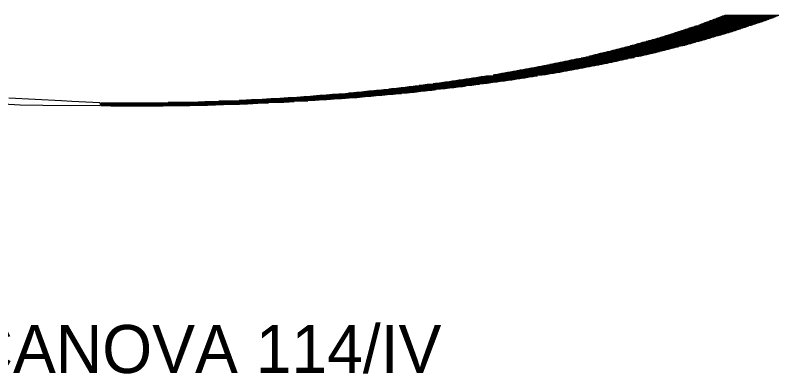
# Model space of a CAD drawing. Extents: x -706655 to -706193, y -1036183 to -1035040.
# Drawn here: x -706307.75 to -706295.83, y -1035256.56 to -1035250.97 of the extents above; entities that cross this region are included whole.
import ezdxf

# ---------------------------------------------------------------- set-up
doc = ezdxf.new("R2010")
doc.units = 0
doc.layers.add('Vrstva 54', color=7, linetype='Continuous')

msp = doc.modelspace()

# ---------------------------------------------------------------- linework, layer by layer
at = {"layer": 'Vrstva 54'}
for p, q in [((-706296.695, -1035250.975), (-706295.853, -1035250.975)), ((-706296.685, -1035250.971), (-706295.842, -1035250.971)), ((-706296.674, -1035250.968), (-706295.83, -1035250.968)), ((-706297.006, -1035251.091), (-706296.173, -1035251.091)), ((-706296.995, -1035251.088), (-706296.161, -1035251.088)), ((-706296.983, -1035251.082), (-706296.149, -1035251.082)), ((-706296.973, -1035251.08), (-706296.137, -1035251.08)), ((-706296.962, -1035251.075), (-706296.126, -1035251.075)), ((-706296.951, -1035251.07), (-706296.113, -1035251.07)), ((-706296.941, -1035251.068), (-706296.101, -1035251.068)), ((-706296.929, -1035251.063), (-706296.088, -1035251.063)), ((-706296.92, -1035251.059), (-706296.076, -1035251.059)), ((-706296.909, -1035251.055), (-706296.064, -1035251.055)), ((-706296.899, -1035251.052), (-706296.052, -1035251.052)), ((-706296.888, -1035251.048), (-706296.041, -1035251.048)), ((-706296.877, -1035251.043), (-706296.029, -1035251.043)), ((-706296.867, -1035251.04), (-706296.019, -1035251.04)), ((-706296.856, -1035251.036), (-706296.008, -1035251.036)), ((-706296.844, -1035251.031), (-706295.997, -1035251.031)), ((-706296.835, -1035251.027), (-706295.987, -1035251.027)), ((-706296.814, -1035251.02), (-706295.965, -1035251.02)), ((-706296.803, -1035251.015), (-706295.957, -1035251.015)), ((-706296.793, -1035251.013), (-706295.946, -1035251.013)), ((-706296.781, -1035251.008), (-706295.935, -1035251.008)), ((-706296.771, -1035251.004), (-706295.926, -1035251.004)), ((-706296.76, -1035251.001), (-706295.914, -1035251.001)), ((-706296.749, -1035250.994), (-706295.903, -1035250.994)), ((-706296.739, -1035250.992), (-706295.893, -1035250.992)), ((-706296.727, -1035250.987), (-706295.883, -1035250.987)), ((-706296.717, -1035250.984), (-706295.874, -1035250.984)), ((-706296.707, -1035250.979), (-706295.863, -1035250.979)), ((-706297.361, -1035251.21), (-706296.536, -1035251.21)), ((-706297.347, -1035251.208), (-706296.524, -1035251.208)), ((-706297.335, -1035251.203), (-706296.512, -1035251.203)), ((-706297.324, -1035251.198), (-706296.499, -1035251.198)), ((-706297.311, -1035251.196), (-706296.487, -1035251.196)), ((-706297.299, -1035251.192), (-706296.475, -1035251.192)), ((-706297.287, -1035251.186), (-706296.463, -1035251.186)), ((-706297.275, -1035251.184), (-706296.452, -1035251.184)), ((-706297.262, -1035251.179), (-706296.439, -1035251.179)), ((-706297.25, -1035251.177), (-706296.428, -1035251.177)), ((-706297.238, -1035251.171), (-706296.415, -1035251.171)), ((-706297.225, -1035251.166), (-706296.402, -1035251.166)), ((-706297.213, -1035251.163), (-706296.391, -1035251.163)), ((-706297.201, -1035251.159), (-706296.38, -1035251.159)), ((-706297.188, -1035251.155), (-706296.367, -1035251.155)), ((-706297.176, -1035251.152), (-706296.356, -1035251.152)), ((-706297.163, -1035251.147), (-706296.343, -1035251.147)), ((-706297.151, -1035251.145), (-706296.33, -1035251.145)), ((-706297.14, -1035251.14), (-706296.319, -1035251.14)), ((-706297.127, -1035251.135), (-706296.307, -1035251.135)), ((-706297.115, -1035251.132), (-706296.295, -1035251.132)), ((-706297.081, -1035251.12), (-706296.259, -1035251.12)), ((-706297.07, -1035251.115), (-706296.247, -1035251.115)), ((-706297.059, -1035251.112), (-706296.234, -1035251.112)), ((-706297.049, -1035251.106), (-706296.222, -1035251.106)), ((-706297.038, -1035251.103), (-706296.21, -1035251.103)), ((-706297.027, -1035251.101), (-706296.198, -1035251.101)), ((-706297.017, -1035251.095), (-706296.186, -1035251.095)), ((-706297.741, -1035251.33), (-706296.943, -1035251.33)), ((-706297.727, -1035251.327), (-706296.927, -1035251.327)), ((-706297.713, -1035251.323), (-706296.914, -1035251.323)), ((-706297.699, -1035251.32), (-706296.9, -1035251.32)), ((-706297.683, -1035251.314), (-706296.886, -1035251.314)), ((-706297.67, -1035251.312), (-706296.873, -1035251.312)), ((-706297.655, -1035251.306), (-706296.859, -1035251.306)), ((-706297.642, -1035251.305), (-706296.844, -1035251.305)), ((-706297.63, -1035251.299), (-706296.831, -1035251.299)), ((-706297.618, -1035251.295), (-706296.818, -1035251.295)), ((-706297.605, -1035251.291), (-706296.805, -1035251.291)), ((-706297.593, -1035251.286), (-706296.79, -1035251.286)), ((-706297.581, -1035251.283), (-706296.778, -1035251.283)), ((-706297.568, -1035251.279), (-706296.762, -1035251.279)), ((-706297.557, -1035251.275), (-706296.748, -1035251.275)), ((-706297.544, -1035251.271), (-706296.734, -1035251.271)), ((-706297.532, -1035251.268), (-706296.721, -1035251.268)), ((-706297.52, -1035251.263), (-706296.708, -1035251.263)), ((-706297.506, -1035251.259), (-706296.693, -1035251.259)), ((-706297.494, -1035251.256), (-706296.68, -1035251.256)), ((-706297.482, -1035251.251), (-706296.666, -1035251.251)), ((-706297.47, -1035251.247), (-706296.653, -1035251.247)), ((-706297.459, -1035251.244), (-706296.639, -1035251.244)), ((-706297.446, -1035251.238), (-706296.626, -1035251.238)), ((-706297.433, -1035251.236), (-706296.611, -1035251.236)), ((-706297.421, -1035251.23), (-706296.598, -1035251.23)), ((-706297.409, -1035251.229), (-706296.584, -1035251.229)), ((-706297.398, -1035251.223), (-706296.572, -1035251.223)), ((-706297.384, -1035251.219), (-706296.56, -1035251.219)), ((-706297.373, -1035251.216), (-706296.548, -1035251.216)), ((-706298.158, -1035251.447), (-706297.362, -1035251.447)), ((-706298.145, -1035251.442), (-706297.346, -1035251.442)), ((-706298.13, -1035251.439), (-706297.33, -1035251.439)), ((-706298.117, -1035251.435), (-706297.315, -1035251.435)), ((-706298.102, -1035251.432), (-706297.299, -1035251.432)), ((-706298.087, -1035251.427), (-706297.284, -1035251.427)), ((-706298.073, -1035251.423), (-706297.268, -1035251.423)), ((-706298.058, -1035251.42), (-706297.251, -1035251.42)), ((-706298.044, -1035251.414), (-706297.237, -1035251.414)), ((-706298.03, -1035251.41), (-706297.22, -1035251.41)), ((-706298.015, -1035251.407), (-706297.205, -1035251.407)), ((-706298.001, -1035251.402), (-706297.19, -1035251.402)), ((-706297.986, -1035251.4), (-706297.176, -1035251.4)), ((-706297.972, -1035251.395), (-706297.162, -1035251.395)), ((-706297.958, -1035251.39), (-706297.148, -1035251.39)), ((-706297.944, -1035251.388), (-706297.135, -1035251.388)), ((-706297.928, -1035251.383), (-706297.121, -1035251.383)), ((-706297.899, -1035251.374), (-706297.092, -1035251.374)), ((-706297.886, -1035251.37), (-706297.079, -1035251.37)), ((-706297.871, -1035251.367), (-706297.065, -1035251.367)), ((-706297.857, -1035251.363), (-706297.051, -1035251.363)), ((-706297.841, -1035251.36), (-706297.038, -1035251.36)), ((-706297.828, -1035251.356), (-706297.025, -1035251.356)), ((-706297.813, -1035251.35), (-706297.01, -1035251.35)), ((-706297.8, -1035251.346), (-706296.996, -1035251.346)), ((-706297.786, -1035251.344), (-706296.983, -1035251.344)), ((-706297.77, -1035251.339), (-706296.97, -1035251.339)), ((-706297.755, -1035251.335), (-706296.955, -1035251.335)), ((-706298.65, -1035251.57), (-706297.852, -1035251.57)), ((-706298.635, -1035251.566), (-706297.834, -1035251.566)), ((-706298.619, -1035251.562), (-706297.819, -1035251.562)), ((-706298.602, -1035251.559), (-706297.802, -1035251.559)), ((-706298.585, -1035251.555), (-706297.787, -1035251.555)), ((-706298.569, -1035251.55), (-706297.772, -1035251.55)), ((-706298.553, -1035251.547), (-706297.755, -1035251.547)), ((-706298.537, -1035251.543), (-706297.74, -1035251.543)), ((-706298.521, -1035251.538), (-706297.724, -1035251.538)), ((-706298.505, -1035251.534), (-706297.709, -1035251.534)), ((-706298.488, -1035251.531), (-706297.694, -1035251.531)), ((-706298.456, -1035251.523), (-706297.661, -1035251.523)), ((-706298.438, -1035251.518), (-706297.646, -1035251.518)), ((-706298.423, -1035251.514), (-706297.63, -1035251.514)), ((-706298.407, -1035251.512), (-706297.614, -1035251.512)), ((-706298.391, -1035251.507), (-706297.598, -1035251.507)), ((-706298.376, -1035251.503), (-706297.582, -1035251.503)), ((-706298.358, -1035251.497), (-706297.567, -1035251.497)), ((-706298.342, -1035251.495), (-706297.551, -1035251.495)), ((-706298.326, -1035251.49), (-706297.536, -1035251.49)), ((-706298.31, -1035251.486), (-706297.52, -1035251.486)), ((-706298.294, -1035251.483), (-706297.504, -1035251.483)), ((-706298.278, -1035251.478), (-706297.489, -1035251.478)), ((-706298.262, -1035251.474), (-706297.473, -1035251.474)), ((-706298.245, -1035251.471), (-706297.457, -1035251.471)), ((-706298.232, -1035251.467), (-706297.442, -1035251.467)), ((-706298.217, -1035251.463), (-706297.424, -1035251.463)), ((-706298.204, -1035251.46), (-706297.409, -1035251.46)), ((-706298.188, -1035251.455), (-706297.393, -1035251.455)), ((-706299.189, -1035251.69), (-706298.402, -1035251.69)), ((-706299.169, -1035251.686), (-706298.383, -1035251.686)), ((-706299.15, -1035251.683), (-706298.365, -1035251.683)), ((-706299.13, -1035251.678), (-706298.346, -1035251.678)), ((-706299.109, -1035251.676), (-706298.329, -1035251.676)), ((-706299.091, -1035251.67), (-706298.31, -1035251.67)), ((-706299.071, -1035251.665), (-706298.293, -1035251.665)), ((-706299.052, -1035251.662), (-706298.273, -1035251.662)), ((-706299.032, -1035251.657), (-706298.255, -1035251.657)), ((-706299.013, -1035251.655), (-706298.237, -1035251.655)), ((-706298.993, -1035251.65), (-706298.218, -1035251.65)), ((-706298.974, -1035251.646), (-706298.2, -1035251.646)), ((-706298.953, -1035251.643), (-706298.181, -1035251.643)), ((-706298.915, -1035251.633), (-706298.145, -1035251.633)), ((-706298.896, -1035251.631), (-706298.128, -1035251.631)), ((-706298.877, -1035251.627), (-706298.109, -1035251.627)), ((-706298.861, -1035251.625), (-706298.09, -1035251.625)), ((-706298.844, -1035251.618), (-706298.071, -1035251.618)), ((-706298.796, -1035251.606), (-706298.016, -1035251.606)), ((-706298.78, -1035251.603), (-706297.997, -1035251.603)), ((-706298.764, -1035251.599), (-706297.98, -1035251.599)), ((-706298.747, -1035251.594), (-706297.962, -1035251.594)), ((-706298.731, -1035251.592), (-706297.944, -1035251.592)), ((-706298.716, -1035251.586), (-706297.925, -1035251.586)), ((-706298.699, -1035251.582), (-706297.906, -1035251.582)), ((-706298.682, -1035251.578), (-706297.889, -1035251.578)), ((-706298.666, -1035251.575), (-706297.871, -1035251.575)), ((-706299.803, -1035251.81), (-706299.017, -1035251.81)), ((-706299.78, -1035251.805), (-706298.996, -1035251.805)), ((-706299.758, -1035251.803), (-706298.975, -1035251.803)), ((-706299.736, -1035251.798), (-706298.953, -1035251.798)), ((-706299.715, -1035251.793), (-706298.932, -1035251.793)), ((-706299.692, -1035251.79), (-706298.911, -1035251.79)), ((-706299.67, -1035251.786), (-706298.89, -1035251.786)), ((-706299.649, -1035251.783), (-706298.869, -1035251.783)), ((-706299.626, -1035251.779), (-706298.847, -1035251.779)), ((-706299.604, -1035251.773), (-706298.826, -1035251.773)), ((-706299.582, -1035251.77), (-706298.805, -1035251.77)), ((-706299.56, -1035251.766), (-706298.785, -1035251.766)), ((-706299.541, -1035251.761), (-706298.763, -1035251.761)), ((-706299.521, -1035251.759), (-706298.742, -1035251.759)), ((-706299.501, -1035251.754), (-706298.721, -1035251.754)), ((-706299.481, -1035251.751), (-706298.701, -1035251.751)), ((-706299.462, -1035251.746), (-706298.679, -1035251.746)), ((-706299.441, -1035251.742), (-706298.658, -1035251.742)), ((-706299.423, -1035251.739), (-706298.636, -1035251.739)), ((-706299.404, -1035251.733), (-706298.615, -1035251.733)), ((-706299.385, -1035251.729), (-706298.594, -1035251.729)), ((-706299.364, -1035251.726), (-706298.573, -1035251.726)), ((-706299.344, -1035251.722), (-706298.552, -1035251.722)), ((-706299.325, -1035251.718), (-706298.531, -1035251.718)), ((-706299.305, -1035251.715), (-706298.512, -1035251.715)), ((-706299.287, -1035251.71), (-706298.494, -1035251.71)), ((-706299.265, -1035251.707), (-706298.476, -1035251.707)), ((-706299.246, -1035251.701), (-706298.458, -1035251.701)), ((-706299.227, -1035251.698), (-706298.438, -1035251.698)), ((-706299.209, -1035251.694), (-706298.42, -1035251.694)), ((-706300.478, -1035251.925), (-706299.698, -1035251.925)), ((-706300.45, -1035251.922), (-706299.673, -1035251.922)), ((-706300.424, -1035251.918), (-706299.649, -1035251.918)), ((-706300.398, -1035251.912), (-706299.624, -1035251.912)), ((-706300.372, -1035251.911), (-706299.598, -1035251.911)), ((-706300.292, -1035251.898), (-706299.523, -1035251.898)), ((-706300.267, -1035251.893), (-706299.498, -1035251.893)), ((-706300.244, -1035251.89), (-706299.474, -1035251.89)), ((-706300.221, -1035251.886), (-706299.448, -1035251.886)), ((-706300.2, -1035251.882), (-706299.423, -1035251.882)), ((-706300.177, -1035251.879), (-706299.399, -1035251.879)), ((-706300.156, -1035251.874), (-706299.374, -1035251.874)), ((-706300.134, -1035251.87), (-706299.349, -1035251.87)), ((-706300.111, -1035251.866), (-706299.324, -1035251.866)), ((-706300.09, -1035251.861), (-706299.3, -1035251.861)), ((-706300.068, -1035251.858), (-706299.273, -1035251.858)), ((-706300.046, -1035251.855), (-706299.249, -1035251.855)), ((-706300.023, -1035251.85), (-706299.228, -1035251.85)), ((-706300.001, -1035251.848), (-706299.207, -1035251.848)), ((-706299.979, -1035251.842), (-706299.185, -1035251.842)), ((-706299.934, -1035251.835), (-706299.144, -1035251.835)), ((-706299.913, -1035251.829), (-706299.122, -1035251.829)), ((-706299.891, -1035251.826), (-706299.1, -1035251.826)), ((-706299.869, -1035251.822), (-706299.08, -1035251.822)), ((-706299.847, -1035251.818), (-706299.059, -1035251.818)), ((-706299.824, -1035251.815), (-706299.038, -1035251.815)), ((-706301.319, -1035252.046), (-706300.532, -1035252.046)), ((-706301.287, -1035252.042), (-706300.502, -1035252.042)), ((-706301.225, -1035252.035), (-706300.442, -1035252.035)), ((-706301.193, -1035252.029), (-706300.414, -1035252.029)), ((-706301.161, -1035252.026), (-706300.384, -1035252.026)), ((-706301.13, -1035252.022), (-706300.354, -1035252.022)), ((-706301.099, -1035252.018), (-706300.325, -1035252.018)), ((-706301.068, -1035252.014), (-706300.295, -1035252.014)), ((-706301.036, -1035252.009), (-706300.264, -1035252.009)), ((-706301.004, -1035252.007), (-706300.235, -1035252.007)), ((-706300.977, -1035252.001), (-706300.205, -1035252.001)), ((-706300.951, -1035251.998), (-706300.175, -1035251.998)), ((-706300.925, -1035251.993), (-706300.146, -1035251.993)), ((-706300.898, -1035251.99), (-706300.115, -1035251.99)), ((-706300.872, -1035251.985), (-706300.086, -1035251.985)), ((-706300.845, -1035251.983), (-706300.056, -1035251.983)), ((-706300.819, -1035251.977), (-706300.027, -1035251.977)), ((-706300.793, -1035251.975), (-706299.998, -1035251.975)), ((-706300.766, -1035251.97), (-706299.973, -1035251.97)), ((-706300.74, -1035251.966), (-706299.948, -1035251.966)), ((-706300.714, -1035251.962), (-706299.923, -1035251.962)), ((-706300.661, -1035251.953), (-706299.872, -1035251.953)), ((-706300.635, -1035251.951), (-706299.848, -1035251.951)), ((-706300.608, -1035251.946), (-706299.823, -1035251.946)), ((-706300.583, -1035251.943), (-706299.798, -1035251.943)), ((-706300.556, -1035251.938), (-706299.773, -1035251.938)), ((-706300.529, -1035251.933), (-706299.749, -1035251.933)), ((-706300.503, -1035251.931), (-706299.724, -1035251.931)), ((-706302.389, -1035252.166), (-706301.523, -1035252.166)), ((-706302.348, -1035252.162), (-706301.488, -1035252.162)), ((-706302.309, -1035252.156), (-706301.454, -1035252.156)), ((-706302.27, -1035252.155), (-706301.419, -1035252.155)), ((-706302.231, -1035252.15), (-706301.384, -1035252.15)), ((-706302.192, -1035252.145), (-706301.351, -1035252.145)), ((-706302.153, -1035252.141), (-706301.317, -1035252.141)), ((-706302.114, -1035252.137), (-706301.282, -1035252.137)), ((-706302.075, -1035252.135), (-706301.248, -1035252.135)), ((-706302.035, -1035252.13), (-706301.212, -1035252.13)), ((-706301.996, -1035252.126), (-706301.18, -1035252.126)), ((-706301.918, -1035252.118), (-706301.111, -1035252.118)), ((-706301.879, -1035252.113), (-706301.076, -1035252.113)), ((-706301.84, -1035252.111), (-706301.041, -1035252.111)), ((-706301.8, -1035252.105), (-706301.009, -1035252.105)), ((-706301.761, -1035252.103), (-706300.974, -1035252.103)), ((-706301.729, -1035252.097), (-706300.939, -1035252.097)), ((-706301.697, -1035252.094), (-706300.905, -1035252.094)), ((-706301.666, -1035252.088), (-706300.871, -1035252.088)), ((-706301.634, -1035252.085), (-706300.837, -1035252.085)), ((-706301.603, -1035252.08), (-706300.803, -1035252.08)), ((-706301.571, -1035252.079), (-706300.77, -1035252.079)), ((-706301.539, -1035252.074), (-706300.74, -1035252.074)), ((-706301.508, -1035252.07), (-706300.711, -1035252.07)), ((-706301.445, -1035252.061), (-706300.652, -1035252.061)), ((-706301.413, -1035252.058), (-706300.621, -1035252.058)), ((-706301.382, -1035252.053), (-706300.591, -1035252.053)), ((-706301.351, -1035252.05), (-706300.563, -1035252.05)), ((-706304.063, -1035252.285), (-706302.95, -1035252.285)), ((-706303.981, -1035252.281), (-706302.892, -1035252.281)), ((-706303.897, -1035252.278), (-706302.833, -1035252.278)), ((-706303.828, -1035252.273), (-706302.774, -1035252.273)), ((-706303.76, -1035252.269), (-706302.716, -1035252.269)), ((-706303.693, -1035252.266), (-706302.657, -1035252.266)), ((-706303.624, -1035252.262), (-706302.598, -1035252.262)), ((-706303.557, -1035252.257), (-706302.539, -1035252.257)), ((-706303.49, -1035252.252), (-706302.481, -1035252.252)), ((-706303.423, -1035252.25), (-706302.422, -1035252.25)), ((-706303.354, -1035252.245), (-706302.378, -1035252.245)), ((-706303.299, -1035252.241), (-706302.334, -1035252.241)), ((-706303.249, -1035252.238), (-706302.29, -1035252.238)), ((-706303.148, -1035252.23), (-706302.203, -1035252.23)), ((-706303.099, -1035252.226), (-706302.16, -1035252.226)), ((-706303.048, -1035252.222), (-706302.116, -1035252.222)), ((-706302.999, -1035252.217), (-706302.072, -1035252.217)), ((-706302.949, -1035252.214), (-706302.028, -1035252.214)), ((-706302.897, -1035252.208), (-706301.984, -1035252.208)), ((-706302.848, -1035252.206), (-706301.94, -1035252.206)), ((-706302.798, -1035252.201), (-706301.895, -1035252.201)), ((-706302.748, -1035252.198), (-706301.852, -1035252.198)), ((-706302.698, -1035252.194), (-706301.81, -1035252.194)), ((-706302.598, -1035252.187), (-706301.721, -1035252.187)), ((-706302.547, -1035252.181), (-706301.677, -1035252.181)), ((-706302.506, -1035252.177), (-706301.633, -1035252.177)), ((-706302.465, -1035252.173), (-706301.591, -1035252.173)), ((-706302.426, -1035252.169), (-706301.556, -1035252.169)), ((-706306.899, -1035252.378), (-706306.431, -1035252.37)), ((-706306.419, -1035252.37), (-706304.751, -1035252.37)), ((-706306.419, -1035252.373), (-706304.876, -1035252.373)), ((-706306.419, -1035252.378), (-706305.03, -1035252.378)), ((-706306.418, -1035252.333), (-706303.8, -1035252.333)), ((-706306.418, -1035252.337), (-706303.884, -1035252.337)), ((-706306.418, -1035252.34), (-706303.965, -1035252.34)), ((-706306.418, -1035252.346), (-706304.045, -1035252.346)), ((-706306.418, -1035252.348), (-706304.125, -1035252.348)), ((-706306.418, -1035252.355), (-706304.25, -1035252.355)), ((-706306.418, -1035252.357), (-706304.376, -1035252.357)), ((-706306.418, -1035252.362), (-706304.5, -1035252.362)), ((-706306.418, -1035252.366), (-706304.625, -1035252.366)), ((-706306.26, -1035252.381), (-706305.446, -1035252.381)), ((-706305.364, -1035252.326), (-706303.639, -1035252.326)), ((-706305.09, -1035252.322), (-706303.557, -1035252.322)), ((-706304.899, -1035252.317), (-706303.477, -1035252.317)), ((-706304.792, -1035252.313), (-706303.397, -1035252.313)), ((-706304.577, -1035252.305), (-706303.245, -1035252.305)), ((-706304.469, -1035252.302), (-706303.184, -1035252.302)), ((-706304.256, -1035252.294), (-706303.068, -1035252.294)), ((-706304.148, -1035252.289), (-706303.009, -1035252.289))]:
    msp.add_line(p, q, dxfattribs=at)
msp.add_lwpolyline([(-706308.735, -1035252.302), (-706307.679, -1035252.367), (-706307.325, -1035252.37), (-706306.444, -1035252.378), (-706306.42, -1035252.367), (-706306.431, -1035252.333), (-706306.868, -1035252.315), (-706307.03, -1035252.301), (-706307.855, -1035252.262)], dxfattribs=at)

# ---------------------------------------------------------------- texts
msp.add_text(' ROKYCANOVA 114/IV', height=0.75, rotation=0, dxfattribs=at).set_placement((-706311.634, -1035256.553))

doc.saveas('drawing.dxf')
